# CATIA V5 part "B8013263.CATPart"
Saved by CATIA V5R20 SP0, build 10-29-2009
Part number: B8013263
Revision: 8
Definition: design
Nomenclature: B8013263
Source: made
Description: NOT SPECIFIED
Bounding box of the stored display mesh (mm): x -28 to 28, y -28 to 28, z 0 to 63
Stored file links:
  C:\Users\Utente\Desktop\3D files B801\B8013263.CATPart
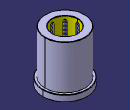
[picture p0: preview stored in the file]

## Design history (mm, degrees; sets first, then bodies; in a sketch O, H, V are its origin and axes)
Body1 "MANIFOLD_SOLID_BREP #38" (main body)
  Solid1: solid without history
Body2 "MANIFOLD_SOLID_BREP #76"
  Solid2: solid without history
Body3 "MANIFOLD_SOLID_BREP #114"
  Solid3: solid without history
Body4 "MANIFOLD_SOLID_BREP #152"
  Solid4: solid without history
Body5 "MANIFOLD_SOLID_BREP #190"
  Solid5: solid without history
Body6 "MANIFOLD_SOLID_BREP #228"
  Solid6: solid without history
Body7 "MANIFOLD_SOLID_BREP #266"
  Solid7: solid without history
Body8 "MANIFOLD_SOLID_BREP #304"
  Solid8: solid without history
Body9 "MANIFOLD_SOLID_BREP #342"
  Solid9: solid without history
Body10 "MANIFOLD_SOLID_BREP #2292"
  Solid10: solid without history
Body11 "MANIFOLD_SOLID_BREP #2330"
  Solid11: solid without history
Body12 "MANIFOLD_SOLID_BREP #2368"
  Solid12: solid without history
Body13 "MANIFOLD_SOLID_BREP #2406"
  Solid13: solid without history
Body14 "MANIFOLD_SOLID_BREP #2444"
  Solid14: solid without history
Body15 "MANIFOLD_SOLID_BREP #2482"
  Solid15: solid without history
Body16 "MANIFOLD_SOLID_BREP #2520"
  Solid16: solid without history
Body17 "MANIFOLD_SOLID_BREP #2558"
  Solid17: solid without history
Body18 "MANIFOLD_SOLID_BREP #2596"
  Solid18: solid without history
Body19 "MANIFOLD_SOLID_BREP #2634"
  Solid19: solid without history
Body20 "MANIFOLD_SOLID_BREP #2672"
  Solid20: solid without history
Body21 "MANIFOLD_SOLID_BREP #2710"
  Solid21: solid without history
Body22 "MANIFOLD_SOLID_BREP #2748"
  Solid22: solid without history
Body23 "MANIFOLD_SOLID_BREP #2786"
  Solid23: solid without history
Body24 "MANIFOLD_SOLID_BREP #2824"
  Solid24: solid without history
Body25 "MANIFOLD_SOLID_BREP #2862"
  Solid25: solid without history
Body26 "MANIFOLD_SOLID_BREP #2900"
  Solid26: solid without history
Body27 "MANIFOLD_SOLID_BREP #2938"
  Solid27: solid without history
Body28 "MANIFOLD_SOLID_BREP #2976"
  Solid28: solid without history
Body29 "MANIFOLD_SOLID_BREP #3014"
  Solid29: solid without history
Body30 "MANIFOLD_SOLID_BREP #3052"
  Solid30: solid without history
Body31 "MANIFOLD_SOLID_BREP #3090"
  Solid31: solid without history
Body32 "MANIFOLD_SOLID_BREP #3128"
  Solid32: solid without history
Body33 "MANIFOLD_SOLID_BREP #3166"
  Solid33: solid without history
Body34 "MANIFOLD_SOLID_BREP #3204"
  Solid34: solid without history
Body35 "MANIFOLD_SOLID_BREP #3242"
  Solid35: solid without history
Body36 "MANIFOLD_SOLID_BREP #3280"
  Solid36: solid without history
Body37 "MANIFOLD_SOLID_BREP #3318"
  Solid37: solid without history
Body38 "MANIFOLD_SOLID_BREP #3356"
  Solid38: solid without history
Body39 "MANIFOLD_SOLID_BREP #3394"
  Solid39: solid without history
Body40 "MANIFOLD_SOLID_BREP #3432"
  Solid40: solid without history
Body41 "MANIFOLD_SOLID_BREP #3470"
  Solid41: solid without history
Body42 "MANIFOLD_SOLID_BREP #3508"
  Solid42: solid without history
Body43 "MANIFOLD_SOLID_BREP #3546"
  Solid43: solid without history
Body44 "MANIFOLD_SOLID_BREP #3584"
  Solid44: solid without history
Body45 "MANIFOLD_SOLID_BREP #3622"
  Solid45: solid without history
Body46 "MANIFOLD_SOLID_BREP #3660"
  Solid46: solid without history
Body47 "MANIFOLD_SOLID_BREP #3698"
  Solid47: solid without history
Body48 "MANIFOLD_SOLID_BREP #3736"
  Solid48: solid without history
Body49 "MANIFOLD_SOLID_BREP #3774"
  Solid49: solid without history
Body50 "MANIFOLD_SOLID_BREP #3812"
  Solid50: solid without history
Body51 "MANIFOLD_SOLID_BREP #3850"
  Solid51: solid without history
Body52 "MANIFOLD_SOLID_BREP #3888"
  Solid52: solid without history
Body53 "MANIFOLD_SOLID_BREP #3926"
  Solid53: solid without history
Body54 "MANIFOLD_SOLID_BREP #3964"
  Solid54: solid without history
Body55 "MANIFOLD_SOLID_BREP #4002"
  Solid55: solid without history
Body56 "MANIFOLD_SOLID_BREP #4040"
  Solid56: solid without history
Body57 "MANIFOLD_SOLID_BREP #4078"
  Solid57: solid without history
Body58 "MANIFOLD_SOLID_BREP #4116"
  Solid58: solid without history
Body59 "MANIFOLD_SOLID_BREP #4154"
  Solid59: solid without history
Body60 "MANIFOLD_SOLID_BREP #4192"
  Solid60: solid without history
Body61 "MANIFOLD_SOLID_BREP #4230"
  Solid61: solid without history
Body62 "MANIFOLD_SOLID_BREP #4268"
  Solid62: solid without history
Body63 "MANIFOLD_SOLID_BREP #4306"
  Solid63: solid without history
Body64 "MANIFOLD_SOLID_BREP #4344"
  Solid64: solid without history
Body65 "MANIFOLD_SOLID_BREP #4382"
  Solid65: solid without history
Body66 "MANIFOLD_SOLID_BREP #4420"
  Solid66: solid without history
Body67 "MANIFOLD_SOLID_BREP #4458"
  Solid67: solid without history
Body68 "MANIFOLD_SOLID_BREP #4496"
  Solid68: solid without history
Body69 "MANIFOLD_SOLID_BREP #4534"
  Solid69: solid without history
Body70 "MANIFOLD_SOLID_BREP #4572"
  Solid70: solid without history
Body71 "MANIFOLD_SOLID_BREP #4610"
  Solid71: solid without history
Body72 "MANIFOLD_SOLID_BREP #4648"
  Solid72: solid without history
Body73 "MANIFOLD_SOLID_BREP #4686"
  Solid73: solid without history
Body74 "MANIFOLD_SOLID_BREP #4724"
  Solid74: solid without history
Body75 "MANIFOLD_SOLID_BREP #4762"
  Solid75: solid without history
Body76 "MANIFOLD_SOLID_BREP #4800"
  Solid76: solid without history
Body77 "MANIFOLD_SOLID_BREP #4838"
  Solid77: solid without history
Body78 "MANIFOLD_SOLID_BREP #4876"
  Solid78: solid without history
Body79 "MANIFOLD_SOLID_BREP #4914"
  Solid79: solid without history
Body80 "MANIFOLD_SOLID_BREP #4952"
  Solid80: solid without history
Body81 "MANIFOLD_SOLID_BREP #4990"
  Solid81: solid without history
Body82 "MANIFOLD_SOLID_BREP #5028"
  Solid82: solid without history
Body83 "MANIFOLD_SOLID_BREP #5066"
  Solid83: solid without history
Body84 "MANIFOLD_SOLID_BREP #5104"
  Solid84: solid without history
Body85 "MANIFOLD_SOLID_BREP #5142"
  Solid85: solid without history
Body86 "MANIFOLD_SOLID_BREP #5180"
  Solid86: solid without history
Body87 "MANIFOLD_SOLID_BREP #5218"
  Solid87: solid without history
Body88 "MANIFOLD_SOLID_BREP #5256"
  Solid88: solid without history
Body89 "MANIFOLD_SOLID_BREP #5294"
  Solid89: solid without history
Body90 "MANIFOLD_SOLID_BREP #5332"
  Solid90: solid without history
Body91 "MANIFOLD_SOLID_BREP #5370"
  Solid91: solid without history
Body92 "MANIFOLD_SOLID_BREP #5408"
  Solid92: solid without history
Body93 "MANIFOLD_SOLID_BREP #5446"
  Solid93: solid without history
Body94 "MANIFOLD_SOLID_BREP #5484"
  Solid94: solid without history
Body95 "MANIFOLD_SOLID_BREP #5522"
  Solid95: solid without history
Body96 "MANIFOLD_SOLID_BREP #5560"
  Solid96: solid without history
Body97 "MANIFOLD_SOLID_BREP #5598"
  Solid97: solid without history
Body98 "MANIFOLD_SOLID_BREP #5636"
  Solid98: solid without history
Body99 "MANIFOLD_SOLID_BREP #5674"
  Solid99: solid without history
Body100 "MANIFOLD_SOLID_BREP #5712"
  Solid100: solid without history
Body101 "MANIFOLD_SOLID_BREP #5750"
  Solid101: solid without history
Body102 "MANIFOLD_SOLID_BREP #5788"
  Solid102: solid without history
Body103 "MANIFOLD_SOLID_BREP #5826"
  Solid103: solid without history
Body104 "MANIFOLD_SOLID_BREP #5864"
  Solid104: solid without history
Body105 "MANIFOLD_SOLID_BREP #5902"
  Solid105: solid without history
